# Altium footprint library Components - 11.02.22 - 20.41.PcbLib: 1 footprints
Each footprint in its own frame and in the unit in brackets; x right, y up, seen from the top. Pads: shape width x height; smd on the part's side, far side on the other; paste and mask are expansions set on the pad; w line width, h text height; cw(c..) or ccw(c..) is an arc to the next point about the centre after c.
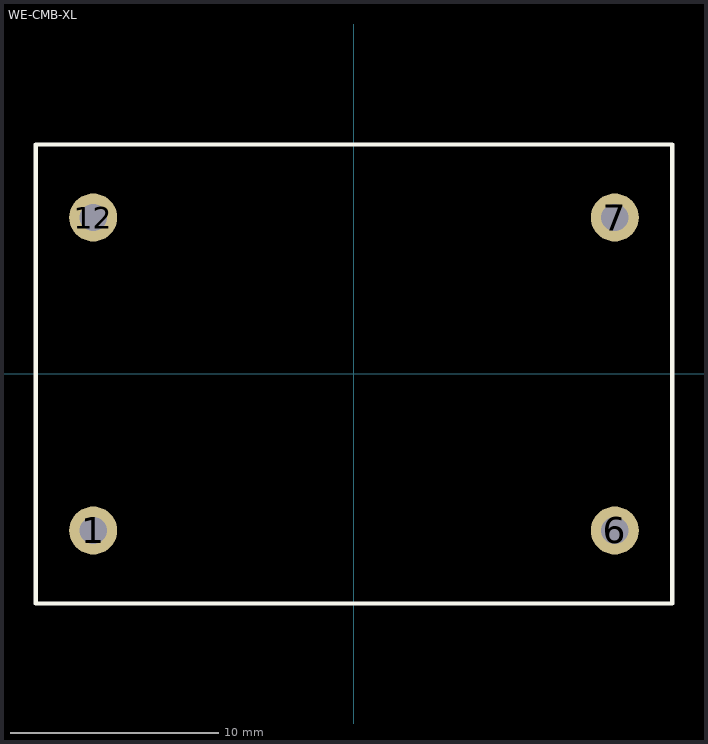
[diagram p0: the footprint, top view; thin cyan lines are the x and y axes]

## WE-CMB-XL [mm] "THT Inductor, 4-Leads, Body 30.0 x 21.0 mm"
height 35
pads (4):
  round 2.3 hole 1.3: 1(-12.5,-7.5) 6(12.5,-7.5) 7(12.5,7.5) 12(-12.5,7.5)
Top Overlay:
  lines w0.2: -15.25,-11 15.25,-11 15.25,11 -15.25,11 -15.25,-11
Mechanical 1:
  lines w0.1: -15.25,-11 15.25,-11 15.25,11 -15.25,11 -15.25,-11
3D body "7448258022.stp": height 35.13, standoff -5, extent -15,-10.5 15,10.5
